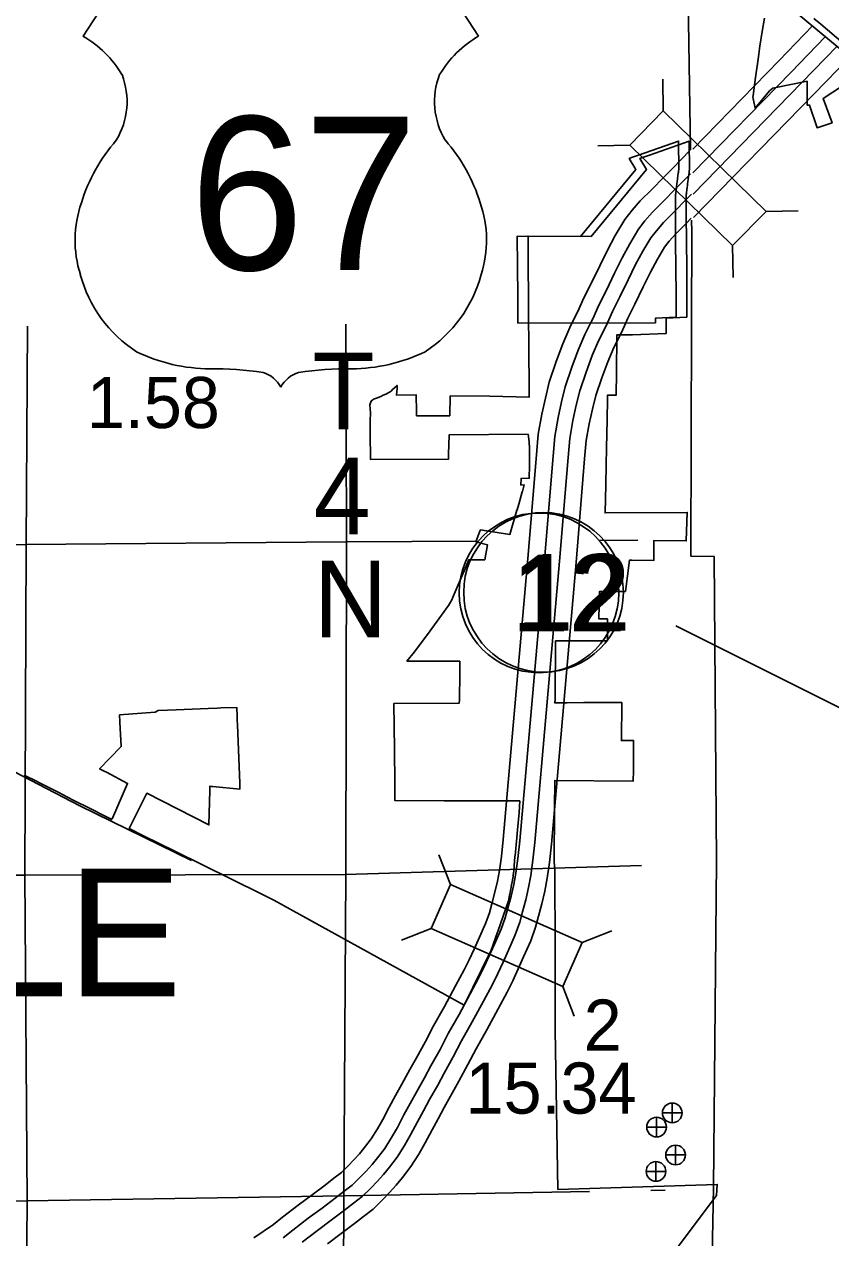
# Model space of a CAD drawing. Extents: x 1127717 to 1741049, y 2026793 to 2244711.
# Drawn here: x 1244840 to 1248173, y 2147909 to 2152924 of the extents above; entities that cross this region are included whole.
import ezdxf

# ---------------------------------------------------------------- set-up
doc = ezdxf.new("R2010")
doc.units = 0
for name, color, linetype in [('10', 7, 'Continuous'), ('15', 7, 'Continuous'), ('16', 7, 'Continuous'), ('2', 7, 'Continuous'), ('20', 7, 'Continuous'), ('22', 7, 'Continuous'), ('25', 7, 'Continuous'), ('26', 7, 'Continuous'), ('27', 7, 'Continuous'), ('30', 7, 'Continuous'), ('5', 7, 'Continuous'), ('58', 7, 'Continuous'), ('6', 7, 'Continuous'), ('7', 7, 'Continuous')]:
    doc.layers.add(name, color=color, linetype=linetype)

msp = doc.modelspace()

# ---------------------------------------------------------------- linework, layer by layer
at = {"layer": '10'}
msp.add_lwpolyline([(1248102.5, 2152948), (1248132.6, 2152923.9), (1248344.2, 2152743.5), (1248369.7, 2152728), (1248401.4, 2152721.2), (1248421.9, 2152722.9), (1248441.8, 2152725.3), (1248475.4, 2152737.5), (1248508, 2152755), (1249376.2, 2153352.3), (1250073.3, 2153826), (1250961.6, 2154441.9), (1251188.5, 2154593.3), (1251228.3, 2154624.9), (1251259.1, 2154659), (1251301.2, 2154710.9), (1251367.6, 2154795.1), (1251772.7, 2155320.6)], dxfattribs=at)
at = {"layer": '15'}
for points in [[(1247602.6, 2152408.5), (1247959.7, 2152774.5), (1248097.4, 2152916.9)], [(1247602.7, 2152310.2), (1248009.1, 2152726.6), (1248149.8, 2152872.2)], [(1247604.1, 2152222.1), (1248053.9, 2152683), (1248199.8, 2152834)], [(1247605.7, 2152125.3), (1248103.2, 2152635.1), (1248250, 2152787)], [(1247103.4, 2151689.3), (1247127.2, 2151736.6), (1247153.1, 2151793.4), (1247184.2, 2151855.2), (1247218, 2151925.6), (1247249.7, 2151990.8), (1247282.4, 2152051.2), (1247321.5, 2152117.2), (1247352.3, 2152155.1), (1247385.9, 2152194.3), (1247433.2, 2152241.7), (1247481.3, 2152291.1), (1247520, 2152329.6), (1247592.6, 2152403.8)], [(1247180.5, 2151689.4), (1247189.3, 2151706.9), (1247215.1, 2151763.7), (1247245.9, 2151824.9), (1247279.9, 2151895.7), (1247310.9, 2151959.3), (1247342.3, 2152017.3), (1247378, 2152077.8), (1247405.1, 2152111.1), (1247436.4, 2152147.6), (1247482.2, 2152193.4), (1247530.2, 2152242.7), (1247568.9, 2152281.2), (1247593, 2152306)], [(1247250, 2151689.5), (1247271.5, 2151736.7), (1247302, 2151797.3), (1247336.1, 2151868.5), (1247366.5, 2151930.7), (1247396.7, 2151986.5), (1247429.5, 2152042), (1247453.1, 2152071), (1247482.3, 2152105.1), (1247526.7, 2152149.6), (1247574.6, 2152198.8), (1247597.4, 2152221.4)], [(1247325.6, 2151689.6), (1247333.5, 2151707), (1247363.7, 2151767), (1247398, 2151838.6), (1247427.6, 2151899.3), (1247456.5, 2151952.6), (1247486, 2152002.6), (1247505.9, 2152027), (1247532.8, 2152058.4), (1247575.6, 2152101.3), (1247596.8, 2152123.1)], [(1245788.7, 2147908.7), (1245869.4, 2147964.4), (1245907.6, 2147994.2), (1245972.2, 2148044.2), (1246030.3, 2148086.9), (1246083.3, 2148126.9), (1246119.8, 2148155.5), (1246150.5, 2148179.1), (1246178.3, 2148206.1), (1246202.5, 2148231.4), (1246224.9, 2148256.3), (1246246.1, 2148282.2), (1246273.1, 2148317.7), (1246299.4, 2148358.9), (1246321.7, 2148397.1), (1246348.4, 2148449.1), (1246374.5, 2148497), (1246400.3, 2148544.2), (1246433.5, 2148603.7), (1246460.5, 2148652.8), (1246497.5, 2148719.5), (1246531.8, 2148785.2), (1246576.5, 2148864.6), (1246622.2, 2148949.6), (1246658.2, 2149016.7), (1246679.2, 2149057.7), (1246699.2, 2149102), (1246721, 2149150.8), (1246747.1, 2149210), (1246762, 2149251.9), (1246772.1, 2149289.5), (1246785.1, 2149337.9), (1246795.7, 2149383), (1246803.8, 2149426.9), (1246812, 2149485.1), (1246819.7, 2149555.5), (1246921.6, 2150716.8), (1246956.5, 2151144.6), (1246963.7, 2151229.6), (1246978.4, 2151313.3), (1246993.8, 2151379.4), (1247009.5, 2151444.9), (1247037.9, 2151530.4), (1247065.8, 2151603.4), (1247094.5, 2151671.4), (1247103.4, 2151689.3)], [(1245910.1, 2147909), (1245949.8, 2147939.9), (1246013.6, 2147989.3), (1246071.4, 2148031.8), (1246125.2, 2148072.4), (1246161.9, 2148101.2), (1246195.6, 2148127), (1246227.2, 2148157.7), (1246252.9, 2148184.7), (1246277, 2148211.4), (1246300.1, 2148239.6), (1246329.6, 2148278.4), (1246358.1, 2148323.1), (1246382, 2148364), (1246409.1, 2148417), (1246434.9, 2148464), (1246460.4, 2148510.9), (1246493.7, 2148570.4), (1246520.7, 2148619.6), (1246558.1, 2148686.9), (1246592.2, 2148752.5), (1246636.7, 2148831.4), (1246682.7, 2148917), (1246719.1, 2148984.8), (1246741.2, 2149028), (1246761.9, 2149073.9), (1246783.8, 2149122.9), (1246811, 2149184.6), (1246827.7, 2149231.4), (1246838.5, 2149271.7), (1246851.8, 2149321.1), (1246863, 2149368.9), (1246871.7, 2149415.9), (1246880.2, 2149476.6), (1246888.1, 2149548.8), (1246990.1, 2150711), (1247025.1, 2151138.9), (1247032, 2151220.7), (1247045.8, 2151299.5), (1247060.7, 2151363.6), (1247075.7, 2151426), (1247102.7, 2151507.3), (1247129.6, 2151577.8), (1247156.9, 2151642.6), (1247180.5, 2151689.4)], [(1245988.2, 2147890.6), (1246051.3, 2147939.4), (1246108.7, 2147981.7), (1246163.3, 2148022.8), (1246200.3, 2148051.8), (1246236.5, 2148079.7), (1246271.6, 2148113.7), (1246298.7, 2148142.1), (1246324.4, 2148170.7), (1246349.1, 2148200.8), (1246380.9, 2148242.6), (1246411.5, 2148290.6), (1246436.8, 2148334), (1246464.4, 2148387.7), (1246489.7, 2148434.1), (1246515.2, 2148480.7), (1246548.4, 2148540.1), (1246575.4, 2148589.4), (1246613.1, 2148657.3), (1246647.2, 2148722.7), (1246691.4, 2148801.3), (1246737.8, 2148887.4), (1246774.5, 2148955.8), (1246797.6, 2149000.9), (1246818.9, 2149048.3), (1246840.9, 2149097.6), (1246869.1, 2149161.5), (1246887.4, 2149212.8), (1246898.8, 2149255.4), (1246912.4, 2149305.9), (1246924.2, 2149356), (1246933.4, 2149405.8), (1246942.3, 2149468.9), (1246950.3, 2149542.7), (1247052.3, 2150705.7), (1247087.3, 2151133.7), (1247094, 2151212.7), (1247107, 2151287.1), (1247121.5, 2151349.2), (1247135.8, 2151408.8), (1247161.5, 2151486.3), (1247187.6, 2151554.5), (1247213.7, 2151616.4), (1247245.7, 2151679.9), (1247250, 2151689.5)], [(1246092.7, 2147884.5), (1246149.8, 2147926.6), (1246205.2, 2147968.3), (1246242.4, 2147997.5), (1246281.6, 2148027.6), (1246320.4, 2148065.3), (1246349.1, 2148095.4), (1246376.6, 2148125.8), (1246403.1, 2148158.2), (1246437.4, 2148203.3), (1246470.2, 2148254.7), (1246497.1, 2148301), (1246525.1, 2148355.5), (1246550.1, 2148401.1), (1246575.3, 2148447.4), (1246608.6, 2148506.8), (1246635.6, 2148556.2), (1246673.6, 2148624.7), (1246707.7, 2148690), (1246751.7, 2148768.1), (1246798.3, 2148854.8), (1246835.4, 2148923.8), (1246859.6, 2148971.1), (1246881.6, 2149020.1), (1246903.8, 2149069.7), (1246933, 2149136.1), (1246953.1, 2149192.3), (1246965.2, 2149237.6), (1246979.1, 2149289.1), (1246991.5, 2149341.9), (1247001.3, 2149394.8), (1247010.5, 2149460.4), (1247018.7, 2149535.9), (1247120.9, 2150699.9), (1247155.9, 2151128), (1247162.3, 2151203.9), (1247174.4, 2151273.4), (1247188.4, 2151333.3), (1247202, 2151389.9), (1247226.3, 2151463.2), (1247251.4, 2151528.9), (1247276.2, 2151587.6), (1247307.7, 2151650.2), (1247325.6, 2151689.6)]]:
    msp.add_lwpolyline(points, dxfattribs=at)
at = {"layer": '16'}
msp.add_lwpolyline([(1247448.8, 2151689.7), (1246880, 2151689)], dxfattribs=at)
at = {"layer": '2'}
for points in [[(1247580.8, 2153200.9), (1247593.3, 2152405.3)], [(1247597.9, 2152114.4), (1247598.7, 2152065.7), (1247597.6, 2151689.9)], [(1247597.6, 2151689.9), (1247594.9, 2150725.5), (1247690.9, 2150725.1), (1247700.5, 2149465), (1247688.4, 2148116.6), (1247661.8, 2146767.3), (1247669.5, 2146213.4)]]:
    msp.add_lwpolyline(points, dxfattribs=at)
at = {"layer": '20'}
for p, q in [((1247480.7, 2152565.7), (1247479.1, 2152697.6)), ((1247342.4, 2152423.9), (1247210.5, 2152422.3)), ((1247905.9, 2152150.8), (1248037.8, 2152152.4)), ((1247767.6, 2152009.1), (1247769.2, 2151877.1)), ((1246601.6, 2149368.5), (1246553.8, 2149491.6)), ((1246521.8, 2149187.3), (1246398.8, 2149139.5)), ((1247145.2, 2149129.1), (1247268.3, 2149176.9)), ((1247065.4, 2148947.9), (1247113.2, 2148824.9))]:
    msp.add_line(p, q, dxfattribs=at)
for points in [[(1247935.6, 2153051.9), (1248392, 2152671.7), (1248518.7, 2152823.9), (1248062.3, 2153204.1)], [(1247905.9, 2152150.8), (1247480.7, 2152565.7), (1247342.4, 2152423.9), (1247767.6, 2152009.1)], [(1246521.8, 2149187.3), (1247065.4, 2148947.9), (1247145.2, 2149129.1), (1246601.6, 2149368.5)]]:
    msp.add_lwpolyline(points, close=True, dxfattribs=at)
at = {"layer": '22'}
for p, q in [((1245256.6, 2153142), (1245083.5, 2152874.3)), ((1246543.5, 2153142), (1246716.6, 2152874.3))]:
    msp.add_line(p, q, dxfattribs=at)
for centre, radius, start, end in [((1244857.3, 2152485.7), 449.7, 30.7809, 59.9883), ((1246942.7, 2152485.7), 449.7, 120.0117, 149.2191), ((1244956.3, 2152604.3), 308.3, 328.8105, 21.2108), ((1246843.8, 2152604.3), 308.3, 158.7892, 211.1895), ((1245762.4, 2151972.5), 719.2, 138.9565, 162.6913), ((1246037.7, 2151972.5), 719.2, 17.3087, 41.0435), ((1245525, 2152031.4), 475.2, 160.9576, 197.3819), ((1246275.1, 2152031.4), 475.2, 342.6181, 19.0424), ((1245602.3, 2152032.7), 549.9, 195.1074, 237.1312), ((1246197.7, 2152032.7), 549.9, 302.8688, 344.8926), ((1245612.6, 2152205.9), 706, 244.0771, 269.5779), ((1246187.5, 2152205.9), 706, 270.4221, 295.9229), ((1245628.9, 2150206.7), 1293.3, 81.1942, 90.9539), ((1245790.6, 2151366.3), 123.9, 28.0342, 72.9864), ((1246009.4, 2151366.3), 123.9, 107.0136, 151.9658), ((1246171.1, 2150206.7), 1293.3, 89.0461, 98.8058)]:
    msp.add_arc(centre, radius, start, end, dxfattribs=at)
at = {"layer": '26'}
for p, q in [((1247477.4, 2148425.1), (1247558.6, 2148425.1)), ((1247518, 2148384.5), (1247518, 2148465.8)), ((1247453.2, 2148325.9), (1247453.2, 2148407.1)), ((1247412.6, 2148366.5), (1247493.8, 2148366.5)), ((1247531.7, 2148210.5), (1247531.7, 2148291.8)), ((1247450.7, 2148142.6), (1247450.7, 2148223.8)), ((1247491.1, 2148251.1), (1247572.4, 2148251.1)), ((1247410.1, 2148183.2), (1247491.3, 2148183.2))]:
    msp.add_line(p, q, dxfattribs=at)
for centre in [(1247518, 2148425.1), (1247453.2, 2148366.5), (1247531.7, 2148251.1), (1247450.7, 2148183.2)]:
    msp.add_circle(centre, 40.6, dxfattribs=at)
at = {"layer": '27'}
for centre in [(1246967.3, 2150574.1), (1246986, 2150576.4)]:
    msp.add_circle(centre, 330, dxfattribs=at)
at = {"layer": '30'}
msp.add_line((1247532.8, 2150437.7), (1248457.1, 2149975.5), dxfattribs=at)
at = {"layer": '5'}
for points in [[(1246159.2, 2147728.1), (1246160.6, 2148082.1), (1246169.1, 2149411.4), (1246171.1, 2150787.1), (1246168.3, 2151684.2)], [(1244848.3, 2147726.4), (1244851.9, 2148062), (1244842.5, 2149408.9), (1244847.7, 2150774.7), (1244852.7, 2151676.2)], [(1243680.3, 2150753.3), (1244846.8, 2150773.7), (1246169.6, 2150785.1), (1246712.4, 2150788.2)], [(1247219.3, 2150791.1), (1247376, 2150792)], [(1243688.9, 2149407.7), (1244842, 2149407.9), (1246168.1, 2149410.8), (1247390.4, 2149448)], [(1243688.9, 2148057.5), (1244852.4, 2148062), (1246161.1, 2148081.6), (1247175.4, 2148099.6)], [(1247429.1, 2148104.1), (1247489.2, 2148105.2)]]:
    msp.add_lwpolyline(points, dxfattribs=at)
at = {"layer": '6'}
for points in [[(1248222.3, 2152670.2), (1248142, 2152617.7), (1248178.7, 2152516.9), (1248116.7, 2152496.1), (1248085.8, 2152589.8), (1248075, 2152590), (1248075, 2152688.7), (1247933.1, 2152660.5), (1247920.4, 2152648.4), (1247860.7, 2152577.2), (1247851.9, 2152617.2), (1247851.6, 2152623.4), (1247852.3, 2152630.3), (1247862.5, 2152703.7), (1247873, 2152780.1), (1247879.8, 2152834), (1247889.7, 2152893.9), (1247899, 2152948.6)], [(1246878.3, 2151924), (1246877.5, 2152048.5), (1247138.3, 2152046.8), (1247366.9, 2152324.3), (1247339.9, 2152369.2), (1247342, 2152370.1), (1247344.2, 2152371), (1247346.9, 2152372.1), (1247350, 2152373.4), (1247366.5, 2152379.2), (1247379.1, 2152383.6), (1247543.9, 2152441.4), (1247544.8, 2152323.7), (1247544, 2152317.5), (1247543.5, 2152313.4), (1247543, 2152309.3), (1247540, 2152285.9), (1247539.3, 2152280.8), (1247538.6, 2152275), (1247536.9, 2152261.7), (1247536.2, 2152256.2), (1247535.5, 2152250.5), (1247532.6, 2152227.6), (1247532.1, 2152224.2), (1247531.6, 2152220.4), (1247531, 2152215.2), (1247531, 2152206.7), (1247531.7, 2152104.5), (1247532, 2152056.8), (1247533.4, 2151886.6), (1247533.7, 2151836.6), (1247533.7, 2151713.9), (1247448.8, 2151710.1), (1247448.8, 2151689.7)], [(1246922.8, 2151924.1), (1246921.9, 2152048.6), (1247182.7, 2152046.9), (1247411.3, 2152324.3), (1247384.3, 2152369.3), (1247386.4, 2152370.2), (1247388.6, 2152371.1), (1247391.3, 2152372.2), (1247394.4, 2152373.5), (1247411, 2152379.3), (1247423.5, 2152383.7), (1247588.3, 2152441.5), (1247589.2, 2152323.8), (1247588.5, 2152317.6), (1247587.9, 2152313.5), (1247587.4, 2152309.4), (1247584.4, 2152286), (1247583.8, 2152280.8), (1247583, 2152275), (1247581.3, 2152261.7), (1247580.6, 2152256.2), (1247579.9, 2152250.5), (1247577, 2152227.7), (1247576.5, 2152224.3), (1247576.1, 2152220.4), (1247575.4, 2152215.3), (1247575.5, 2152206.7), (1247576.1, 2152104.6), (1247576.4, 2152056.9), (1247577.9, 2151886.7), (1247578.1, 2151836.7), (1247578.1, 2151713.9), (1247493.3, 2151710.1), (1247493.3, 2151646.7), (1247353.4, 2151640.5), (1247289.2, 2151641.1), (1247288.3, 2151578.2), (1247287.8, 2151543.3), (1247286.9, 2151485.9), (1247286.1, 2151391.1), (1247250.6, 2151391.4), (1247250.5, 2151386), (1247250.4, 2151383.5), (1247250.3, 2151381.1), (1247250.2, 2151377.3), (1247248.4, 2151287.6), (1247246.1, 2151172.9), (1247244.6, 2151101.3), (1247243, 2151022.1), (1247240.7, 2150904.6), (1247579.7, 2150906.9), (1247576, 2150789.1), (1247442.3, 2150790.6), (1247442.4, 2150708.6), (1247351.4, 2150709), (1247349.4, 2150709), (1247347.7, 2150709), (1247340.7, 2150709), (1247324.6, 2150579.9), (1247217.8, 2150580.5), (1247215.1, 2150466.8), (1247250.3, 2150466.6), (1247249.8, 2150375.6), (1247197.5, 2150376.5), (1247153.8, 2150376.3), (1247097.7, 2150375.9), (1247035.8, 2150375.6), (1247034.4, 2150139.4), (1247034.4, 2150131.5), (1247033.5, 2150128.1), (1247032.8, 2150125.1), (1247032, 2150122.1), (1247031.4, 2150119.9), (1247035, 2150119.9), (1247084, 2150119.9), (1247152.7, 2150120.4), (1247154.4, 2150120.4), (1247156.2, 2150120.5), (1247188.2, 2150120.7), (1247196.1, 2150120.8), (1247210.6, 2150120.9), (1247213.2, 2150120.9), (1247215.7, 2150120.9), (1247272.5, 2150121.4), (1247274.1, 2150121.4), (1247275.9, 2150121.4), (1247309.1, 2150121.7), (1247308.2, 2149964), (1247329.4, 2149963.9), (1247358, 2149963.7), (1247358, 2149957.1), (1247357.7, 2149919.3), (1247357.7, 2149918.3), (1247357.2, 2149845), (1247357.2, 2149840.6), (1247356.8, 2149796.3), (1247032.4, 2149798.2), (1247031.3, 2149682.7), (1247030.5, 2149463.4), (1247033.3, 2149428.2)], [(1246869.4, 2149492.4), (1246869.9, 2149498.6), (1246872.1, 2149522.3), (1246872.9, 2149530.6), (1246873, 2149532.3), (1246873.1, 2149534), (1246874.3, 2149547.3), (1246878.5, 2149595.1), (1246885.3, 2149666.4), (1246887.4, 2149714.2), (1246575.1, 2149714.8), (1246371.7, 2149715.5), (1246370.9, 2149788.6), (1246369.4, 2149927.5), (1246366.9, 2150116.7), (1246637.7, 2150119), (1246637.9, 2150123.6), (1246638, 2150125.8), (1246638.1, 2150128), (1246638.3, 2150131.8), (1246639.6, 2150241.9), (1246639.9, 2150291.9), (1246559, 2150292.4), (1246421.3, 2150292.2), (1246452.4, 2150330.6), (1246480.3, 2150367), (1246506.7, 2150401.7), (1246592.9, 2150522.3), (1246605.3, 2150543.1), (1246612.8, 2150559.4), (1246653.9, 2150655.6), (1246676.8, 2150711.3), (1246743.3, 2150711.1), (1246754.8, 2150772.4), (1246705.5, 2150785.4), (1246723.1, 2150829.7), (1246725, 2150834.5), (1246759.1, 2150829.1), (1246847.2, 2150815.7), (1246876, 2150915.3), (1246876.6, 2150917.3), (1246876.6, 2150917.4), (1246883.4, 2150940.9), (1246898.1, 2150991.7), (1246898.7, 2150993.5), (1246906.5, 2151020.5), (1246892.3, 2151019.9), (1246893.3, 2151047.1), (1246926.8, 2151048), (1246927.4, 2151100.2), (1246928.3, 2151174.4), (1246927.4, 2151183.4), (1246927.1, 2151186.3), (1246926.8, 2151189.1), (1246925.9, 2151198), (1246922.2, 2151229.4), (1246595.9, 2151227), (1246595.7, 2151224.1), (1246593.6, 2151148.2), (1246592.9, 2151126.1), (1246270.1, 2151125.4), (1246271.1, 2151155.5), (1246269.5, 2151203.9), (1246269.4, 2151222.8), (1246269.5, 2151279.2), (1246269.6, 2151296), (1246270.2, 2151307.7), (1246270.3, 2151312), (1246270.1, 2151318), (1246268.5, 2151351.9), (1246271.9, 2151363.3), (1246275.1, 2151368.1), (1246280.9, 2151372.1), (1246283.8, 2151374.1), (1246299.1, 2151380.5), (1246315.6, 2151387.6), (1246320.8, 2151389.9), (1246337.6, 2151397.4), (1246346.5, 2151401.6), (1246351.5, 2151405), (1246355.7, 2151407.9), (1246362.3, 2151414.7), (1246369.9, 2151421.7), (1246380.7, 2151431.6), (1246380.8, 2151419.8), (1246377.6, 2151391.8), (1246459.9, 2151392.3), (1246460.9, 2151324), (1246461.1, 2151306), (1246462.8, 2151306), (1246598.1, 2151306.1), (1246600.6, 2151388.1), (1246763.6, 2151386.9), (1246926.1, 2151382.7), (1246924.9, 2151621.4), (1246924.4, 2151693.4), (1246924.2, 2151723.1), (1246923.9, 2151760.9), (1246923.6, 2151799.5), (1246922.8, 2151924.1)], [(1246880, 2151689), (1246879.9, 2151693.3), (1246879.7, 2151723.1), (1246879.5, 2151760.9), (1246879.2, 2151799.4), (1246878.3, 2151924)], [(1244839.7, 2149821.3), (1244890.7, 2149795.3), (1244902.8, 2149789.1), (1244935.7, 2149772.3), (1244979.4, 2149750), (1245042, 2149718.1), (1245069.4, 2149704.1), (1245084.1, 2149696.6), (1245201, 2149636.9), (1245201.9, 2149638.8), (1245202.9, 2149641.2), (1245204, 2149643.6), (1245267, 2149786.7), (1245179.2, 2149832.5), (1245173.1, 2149835.6), (1245151, 2149847), (1245193.2, 2149890.5), (1245240.5, 2149939.2), (1245235.2, 2150039.7), (1245235.1, 2150041.8), (1245235, 2150043), (1245233.6, 2150069.5), (1245380.9, 2150081.7), (1245393.8, 2150088.3), (1245431.5, 2150089.8), (1245467.3, 2150091.2), (1245500.4, 2150092.5), (1245533.6, 2150093.8), (1245566.7, 2150095.1), (1245599.9, 2150096.4), (1245638.7, 2150097.9), (1245651.9, 2150098.4), (1245718, 2150101), (1245719.5, 2150063.7), (1245720.1, 2150048.4), (1245720.9, 2150029.2), (1245722.2, 2149994.7), (1245723.6, 2149960.2), (1245724.9, 2149925.6), (1245726.2, 2149891.1), (1245727.6, 2149856.6), (1245730.3, 2149788), (1245731.2, 2149763.4), (1245619, 2149773.8), (1245613.6, 2149774.3), (1245606.6, 2149775), (1245606.6, 2149775), (1245606.5, 2149772.9), (1245606.2, 2149757.6), (1245603, 2149615.4), (1245346.7, 2149745.9), (1245346.4, 2149746.1), (1245328.9, 2149711.1), (1245282.9, 2149619.3), (1245276, 2149605.6), (1245275.2, 2149603.9), (1245274.8, 2149603.1), (1245273.3, 2149600.2), (1245273.9, 2149599.9), (1245333.1, 2149570.6), (1245461.6, 2149506.9), (1245573.8, 2149451.4), (1245821.2, 2149328.9), (1245852.4, 2149313.4), (1245862.9, 2149308.2), (1245866.2, 2149306.6), (1245869, 2149305.2), (1245871.8, 2149303.8), (1246658.3, 2148870.6), (1246765.8, 2149089.8), (1246767.5, 2149093.5), (1246796.1, 2149171.9), (1246797.1, 2149174.4), (1246841, 2149301.1), (1246845.9, 2149325.6), (1246846.6, 2149329.1), (1246851.1, 2149351.2), (1246851.9, 2149356.4), (1246852.5, 2149360), (1246857.5, 2149387.3), (1246858, 2149390.9), (1246858.5, 2149393), (1246862.3, 2149418.3), (1246862.9, 2149421.9), (1246866.6, 2149467.5), (1246869.4, 2149492.4)], [(1247033.3, 2149428.2), (1247033.7, 2149098), (1247034.7, 2148766.6), (1247045.6, 2148108.6), (1247703.7, 2148129.6), (1247700.8, 2148083.3), (1247248.4, 2147482.3)]]:
    msp.add_lwpolyline(points, dxfattribs=at)
at = {"layer": '7'}
msp.add_lwpolyline([(1245530.3, 2149468.5), (1245068.9, 2149693.4), (1244726.2, 2149872.1), (1244388.6, 2150062.9), (1244396.8, 2150659)], dxfattribs=at)

# ---------------------------------------------------------------- texts
at = {"layer": '20'}
msp.add_text('2', height=211.2, dxfattribs=at).set_placement((1247152, 2148682.2))
at = {"layer": '22'}
msp.add_text('67', height=633.6, dxfattribs=at).set_placement((1245523.9, 2151908.8))
at = {"layer": '25'}
msp.add_text('15.34', height=211.2, dxfattribs=at).set_placement((1246663.7, 2148422))
at = {"layer": '27'}
for p in [(1246855.1, 2150415.7), (1246873.8, 2150418)]:
    msp.add_text('12', height=316.8, dxfattribs=at).set_placement(p)
at = {"layer": '30'}
for s, p in [('T', (1246030, 2151250.1)), ('4', (1246036, 2150816.5)), ('N', (1246035.1, 2150390.9))]:
    msp.add_text(s, height=316.8, dxfattribs=at).set_placement(p)
at = {"layer": '58'}
msp.add_text('1.58', height=211.2, dxfattribs=at).set_placement((1245098.4, 2151255.3))
at = {"layer": '6'}
msp.add_text('JACKSONVILLE', height=527.999, dxfattribs=at).set_placement((1240232.5, 2148906.7))

doc.saveas('drawing.dxf')
